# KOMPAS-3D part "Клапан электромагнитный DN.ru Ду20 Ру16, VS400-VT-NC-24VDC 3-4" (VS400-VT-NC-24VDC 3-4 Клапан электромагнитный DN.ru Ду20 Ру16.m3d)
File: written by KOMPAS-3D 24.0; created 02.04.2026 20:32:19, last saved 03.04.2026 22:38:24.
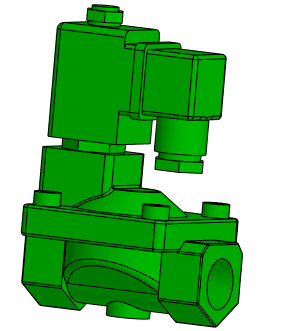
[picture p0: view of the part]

Document properties: Автор: artio; Полное имя файла: C:\Users\artio\OneDrive\Рабочий стол\Клапан электромагнитный DN.ru\VS400-VT-NC\VS400-VT-NC-24VDC 3-4 Клапан электромагнитный DN.ru Ду20 Ру16.m3d

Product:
- Body: Тело 1  | qty 1
    Масса: 1.210539
- Part/product: Клапан электромагнитный DN.ru Ду20 Ру16  | designation VS400-VT-NC-24VDC 3-4
    Масса: 0.954
    Раздел спецификации: Прочие изделия
    Примечание: D130-04734
    additional columns: ef56311e-7521-43dc-8291-0e6108b3d81d; VS400-ET-NC-220VAC 3-4; artio; c; Шероховатость не задана; Да

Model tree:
1. Операция без истории:1

Expressions: VS400-VT-NC-24VDC 3-4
